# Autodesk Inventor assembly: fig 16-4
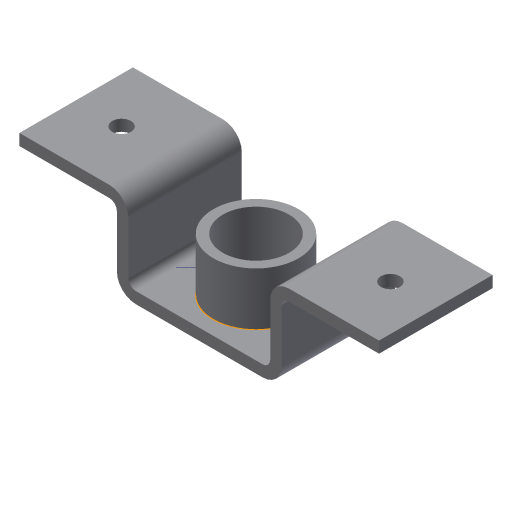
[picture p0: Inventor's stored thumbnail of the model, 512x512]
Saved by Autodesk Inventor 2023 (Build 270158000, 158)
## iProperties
Created: 2004-07
Part Number: fig 16-4
Document SubType Name: Weldment
Designer: CADCIM Technologies
Manufacturer: Standard
Standards Organization: Custom
Author: CADCIM Technologies
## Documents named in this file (3)
- D:\PROJECTS\Project 2022\Autodesk Inventor For Professional 2023\RESOURCES INVENTOR 2023\RESOURCES INVENTOR 2023\Inventor_2023_Part\Inventor_2023_Part\c16_Inv_2023_prt\fig 16-4.iam
- D:\PROJECTS\Project 2022\Autodesk Inventor For Professional 2023\RESOURCES INVENTOR 2023\RESOURCES INVENTOR 2023\Inventor_2023_Part\Inventor_2023_Part\c16_Inv_2023_prt\Bracket.ipt
- D:\PROJECTS\Project 2022\Autodesk Inventor For Professional 2023\RESOURCES INVENTOR 2023\RESOURCES INVENTOR 2023\Inventor_2023_Part\Inventor_2023_Part\c16_Inv_2023_prt\cylinder.ipt
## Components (2 placed, 2 different names)
1. Bracket:1 — Insert:1
2. cylinder:1 — Insert:1
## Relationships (1: Insert 1)
- Insert:1: Bracket:1 ↔ cylinder:1
